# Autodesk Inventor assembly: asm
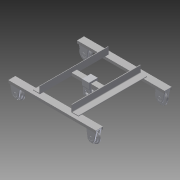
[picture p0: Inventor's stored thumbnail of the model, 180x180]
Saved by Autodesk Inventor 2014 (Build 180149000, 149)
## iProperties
Created: 2009-11
Part Number: asm
Document SubType Name: Assembly
Designer: pokornp
Mass: 1.57077e+06 g
Surface Area: 310738 cm^2
Volume: 253828 cm^3
Density: 6.18831 g/cm^3
_SolveAssemblyDoc: Frame Generator Solve Assembly
_Version: 15.0.0
Author: pokornp
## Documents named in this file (4)
- C:\Users\iTools\Desktop\tutorial files\Frame Analysis 1\analyze_frame.iam
- C:\Users\iTools\Desktop\tutorial files\Frame Analysis 1\chart.iam
- C:\Users\iTools\Desktop\tutorial files\Frame Analysis 1\sub.ipt
- C:\Users\iTools\Desktop\tutorial files\Frame Analysis 1\asm\Frame\Frame0001.iam
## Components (3 placed, 3 different names)
1. chart:1 [sub-assembly] — Tangent:1, Mate:1, Tangent:2, Mate:2
2. sub:1
3. Frame0001:1 [sub-assembly] — Tangent:1, Mate:1, Tangent:2, Mate:2
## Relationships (4: Tangent 2, Mate 2)
- Tangent:1: chart:1 ↔ Frame0001:1
- Mate:1: chart:1 ↔ Frame0001:1
- Tangent:2: chart:1 ↔ Frame0001:1
- Mate:2: chart:1 ↔ Frame0001:1
